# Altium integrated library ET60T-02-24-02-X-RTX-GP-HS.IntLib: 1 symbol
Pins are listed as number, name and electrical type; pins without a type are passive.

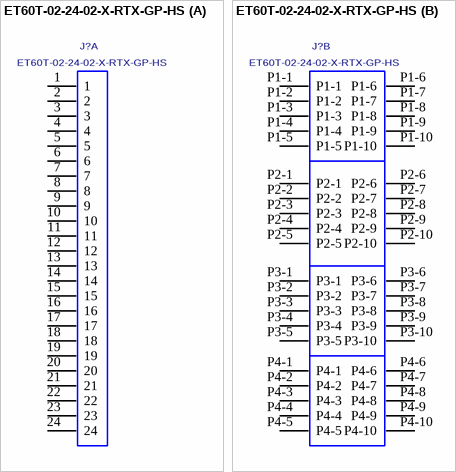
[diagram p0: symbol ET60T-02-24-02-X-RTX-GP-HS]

## ET60T-02-24-02-X-RTX-GP-HS
designator J?
R/A PLUG  TEN60 POWER ASSEMBLY.; MANUFACTURER: SAMTEC
footprint ET60T-02-24-02-X-RTX-GP-HS
part A pins: 1, 2, 3, 4, 5, 6, 7, 8, 9, 10, 11, 12, 13, 14, 15, 16, 17, 18, 19, 20, 21, 22, 23, 24
part B pins: P1-1, P1-2, P1-3, P1-4, P1-5, P1-6, P1-7, P1-8, P1-9, P1-10, P2-1, P2-2, P2-3, P2-4, P2-5, P2-6, P2-7, P2-8, P2-9, P2-10, P3-1, P3-2, P3-3, P3-4, P3-5, P3-6, P3-7, P3-8, P3-9, P3-10, P4-1, P4-2, P4-3, P4-4, P4-5, P4-6, P4-7, P4-8, P4-9, P4-10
